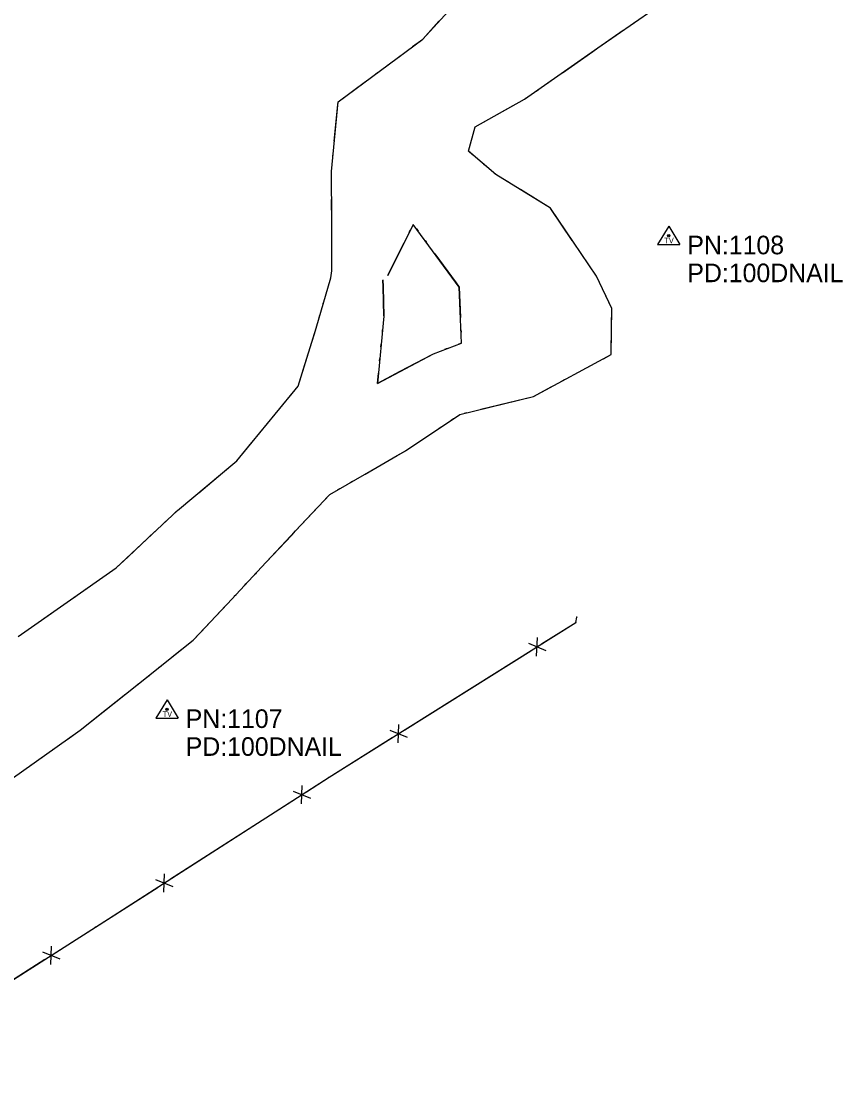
# Model space of a CAD drawing. Extents: x 1282810 to 1284464, y 402460 to 405899.
# Drawn here: x 1283550.7 to 1283771.6, y 403773 to 404059.6 of the extents above; entities that cross this region are included whole.
import ezdxf

# ---------------------------------------------------------------- set-up
doc = ezdxf.new("R2010")
doc.units = 0
for name, color, linetype in [('S_FENCE', 7, 'Continuous'), ('S_MSC_PT_SYM', 7, 'Continuous'), ('S_SECONDARY_CTL', 7, 'Continuous'), ('S_SECONDARY_CTL_ANNOT', 7, 'Continuous'), ('S_STREAM', 7, 'Continuous')]:
    doc.layers.add(name, color=color, linetype=linetype)

msp = doc.modelspace()

# ---------------------------------------------------------------- linework, layer by layer
at = {"layer": 'S_FENCE'}
for p, q in [((1283633.54, 403856.3), (1283699.83, 403897.87)), ((1283699.83, 403897.87), (1283700.13, 403899.37)), ((1283687.14, 403892.33), (1283691.75, 403890.38)), ((1283689.32, 403888.86), (1283689.57, 403893.85)), ((1283649.87, 403868.96), (1283654.48, 403867.01)), ((1283652.05, 403865.49), (1283652.3, 403870.48)), ((1283570.67, 403815.95), (1283633.54, 403856.3)), ((1283623.88, 403852.53), (1283628.51, 403850.63)), ((1283626.09, 403849.08), (1283626.29, 403854.08)), ((1283586.87, 403828.78), (1283591.49, 403826.88)), ((1283589.08, 403825.33), (1283589.28, 403830.33)), ((1283503.36, 403773.04), (1283570.67, 403815.95)), ((1283556.48, 403809.33), (1283561.09, 403807.41)), ((1283558.68, 403805.87), (1283558.88, 403810.86))]:
    msp.add_line(p, q, dxfattribs=at)
for points in [[(1283690.66, 403892.12), (1283699.83, 403897.87)], [(1283699.83, 403897.87), (1283700.13, 403899.37)], [(1283653.87, 403869.05), (1283687.75, 403890.29)], [(1283633.54, 403856.3), (1283650.48, 403866.92)], [(1283627.4, 403852.36), (1283633.54, 403856.3)], [(1283590.86, 403828.91), (1283624.51, 403850.5)], [(1283570.67, 403815.95), (1283587.5, 403826.75)], [(1283559.98, 403809.14), (1283570.67, 403815.95)], [(1283523.51, 403785.88), (1283557.1, 403807.3)]]:
    msp.add_lwpolyline(points, dxfattribs=at)
at = {"layer": 'S_MSC_PT_SYM'}
for points in [[(1283699.83, 403897.87), (1283699.83, 403897.92), (1283699.83, 403897.87), (1283699.78, 403897.87), (1283699.83, 403897.87), (1283699.83, 403897.82), (1283699.83, 403897.87), (1283699.88, 403897.87)], [(1283700.13, 403899.37), (1283700.13, 403899.42), (1283700.13, 403899.37), (1283700.08, 403899.37), (1283700.13, 403899.37), (1283700.13, 403899.32), (1283700.13, 403899.37), (1283700.18, 403899.37)], [(1283633.54, 403856.3), (1283633.54, 403856.35), (1283633.54, 403856.3), (1283633.49, 403856.3), (1283633.54, 403856.3), (1283633.54, 403856.25), (1283633.54, 403856.3), (1283633.59, 403856.3)], [(1283570.67, 403815.95), (1283570.67, 403816), (1283570.67, 403815.95), (1283570.62, 403815.95), (1283570.67, 403815.95), (1283570.67, 403815.9), (1283570.67, 403815.95), (1283570.72, 403815.95)]]:
    msp.add_lwpolyline(points, dxfattribs=at)
at = {"layer": 'S_SECONDARY_CTL'}
for p, q in [((1283724.84, 404004.55), (1283721.83, 403999.6)), ((1283724.84, 404004.55), (1283727.79, 403999.6)), ((1283721.83, 403999.6), (1283727.79, 403999.6)), ((1283589.95, 403877.14), (1283586.94, 403872.19)), ((1283589.95, 403877.14), (1283592.89, 403872.19)), ((1283586.94, 403872.19), (1283592.89, 403872.19))]:
    msp.add_line(p, q, dxfattribs=at)
for centre, radius in [((1283724.84, 404001.94), 0.311), ((1283724.84, 404001.94), 0.183), ((1283724.84, 404001.94), 0.103), ((1283589.95, 403874.53), 0.311), ((1283589.95, 403874.53), 0.183), ((1283589.95, 403874.53), 0.103)]:
    msp.add_circle(centre, radius, dxfattribs=at)
at = {"layer": 'S_STREAM'}
for points in [[(1283549.94, 403894.16), (1283563.09, 403903.37), (1283576.25, 403912.57), (1283592.73, 403928.03), (1283608.69, 403941.37), (1283616.93, 403951.42), (1283625.17, 403961.47), (1283630.02, 403977.03), (1283633.93, 403990.58), (1283634.27, 403992.53), (1283634.2, 404005.88), (1283634.12, 404019.23), (1283635.92, 404037.92), (1283647.29, 404046.35), (1283658.67, 404054.79), (1283674.36, 404072.03)], [(1283548.02, 403855.75), (1283566.59, 403868.95), (1283581.78, 403881.04), (1283596.97, 403893.13), (1283606.15, 403902.93), (1283615.32, 403912.74), (1283624.49, 403922.54), (1283633.67, 403932.34), (1283654.02, 403944.08), (1283668.68, 403953.88), (1283688.48, 403958.73), (1283709.34, 403969.96), (1283709.53, 403982.36), (1283705.39, 403991.08), (1283693, 404009.35), (1283678.32, 404018.42), (1283670.97, 404024.64), (1283672.77, 404031.24), (1283686.01, 404038.64), (1283705.76, 404052.43), (1283725.51, 404066.21)], [(1283655.97, 404052.79), (1283658.67, 404054.79), (1283663.05, 404059.61)], [(1283715.39, 404059.14), (1283715.98, 404059.56)], [(1283704.43, 404051.5), (1283705.76, 404052.43), (1283712.62, 404057.21)], [(1283652.32, 404050.08), (1283652.89, 404050.51)], [(1283696.24, 404045.78), (1283704.43, 404051.49)], [(1283649.15, 404047.73), (1283649.72, 404048.15)], [(1283645.97, 404045.37), (1283646.55, 404045.8)], [(1283692.47, 404043.15), (1283693.06, 404043.56)], [(1283635.85, 404037.23), (1283635.92, 404037.92), (1283643.3, 404043.39)], [(1283689.19, 404040.86), (1283689.78, 404041.27)], [(1283685.91, 404038.58), (1283686.01, 404038.64), (1283686.51, 404038.99)], [(1283634.91, 404027.39), (1283635.85, 404037.22)], [(1283674.25, 404032.07), (1283682.97, 404036.94)], [(1283672.09, 404023.7), (1283670.97, 404024.64), (1283672.77, 404031.24), (1283674.24, 404032.07)], [(1283634.47, 404022.87), (1283634.54, 404023.58)], [(1283675.59, 404020.73), (1283675.04, 404021.19)], [(1283634.12, 404018.93), (1283634.12, 404019.23), (1283634.16, 404019.65)], [(1283678.68, 404018.19), (1283678.32, 404018.42), (1283678.09, 404018.61)], [(1283634.15, 404014.98), (1283634.14, 404015.7)], [(1283682.08, 404016.1), (1283681.46, 404016.48)], [(1283693.29, 404008.92), (1283693, 404009.35), (1283684.95, 404014.33)], [(1283634.22, 404001.78), (1283634.2, 404005.88), (1283634.17, 404011.65)], [(1283698.9, 404000.65), (1283693.3, 404008.92)], [(1283647.92, 403990.03), (1283648.01, 403988.19), (1283648.25, 403980.3), (1283646.5, 403962.19), (1283661.61, 403970.2), (1283669.09, 403973.06), (1283668.52, 403988.14), (1283656.12, 404004.99), (1283649.33, 403991.28)], [(1283655.07, 404002.87), (1283655.38, 404003.5)], [(1283657.01, 404003.78), (1283657.42, 404003.21)], [(1283634.17, 403991.9), (1283634.27, 403992.53), (1283634.22, 404001.77)], [(1283659.3, 404000.66), (1283659.72, 404000.1)], [(1283649.33, 403991.28), (1283653.62, 403999.95)], [(1283661.94, 403997.08), (1283667.67, 403989.3)], [(1283701.48, 403996.84), (1283701.08, 403997.44)], [(1283703.72, 403993.54), (1283703.32, 403994.14)], [(1283648.25, 403980.36), (1283648.01, 403988.19), (1283647.92, 403990.02)], [(1283667.68, 403989.3), (1283668.52, 403988.14), (1283668.83, 403979.91)], [(1283705.83, 403990.15), (1283705.52, 403990.81)], [(1283633.04, 403987.5), (1283633.24, 403988.19)], [(1283709.46, 403977.63), (1283709.53, 403982.36), (1283707.28, 403987.11)], [(1283631.95, 403983.71), (1283632.15, 403984.4)], [(1283630.85, 403979.91), (1283631.05, 403980.6)], [(1283707.29, 403968.86), (1283709.34, 403969.96), (1283709.46, 403977.62)], [(1283626.98, 403967.28), (1283629.92, 403976.71)], [(1283647.83, 403975.93), (1283647.9, 403976.63)], [(1283668.96, 403976.65), (1283668.98, 403975.95)], [(1283647.46, 403972.09), (1283647.52, 403972.78)], [(1283668.84, 403972.96), (1283668.19, 403972.71)], [(1283647.09, 403968.24), (1283647.15, 403968.93)], [(1283661.1, 403969.93), (1283652.56, 403965.41)], [(1283665.23, 403971.58), (1283664.58, 403971.33)], [(1283622.77, 403958.54), (1283625.17, 403961.47), (1283626.98, 403967.28)], [(1283703.24, 403966.68), (1283703.88, 403967.02)], [(1283652.56, 403965.4), (1283646.5, 403962.19), (1283646.77, 403964.99)], [(1283696.21, 403962.89), (1283696.84, 403963.23)], [(1283699.73, 403964.79), (1283700.36, 403965.13)], [(1283684.03, 403957.64), (1283688.48, 403958.73), (1283693.24, 403961.29)], [(1283674.32, 403955.26), (1283684.02, 403957.64)], [(1283619.89, 403955.02), (1283620.34, 403955.57)], [(1283617.38, 403951.97), (1283617.84, 403952.52)], [(1283666.37, 403952.33), (1283666.97, 403952.73)], [(1283669.86, 403954.17), (1283670.56, 403954.34)], [(1283614.88, 403948.91), (1283615.33, 403949.46)], [(1283663.05, 403950.11), (1283663.65, 403950.51)], [(1283606.05, 403939.15), (1283608.69, 403941.37), (1283612.77, 403946.33)], [(1283651.85, 403942.83), (1283654.02, 403944.08), (1283660.24, 403948.24)], [(1283643.19, 403937.84), (1283651.85, 403942.82)], [(1283598.46, 403932.82), (1283606.04, 403939.15)], [(1283639.21, 403935.54), (1283639.84, 403935.9)], [(1283632.58, 403931.18), (1283633.08, 403931.71)], [(1283635.75, 403933.54), (1283636.38, 403933.91)], [(1283594.97, 403929.9), (1283595.52, 403930.36)], [(1283591.98, 403927.33), (1283592.5, 403927.81)], [(1283623.45, 403921.43), (1283624.49, 403922.54), (1283630.28, 403928.72)], [(1283589.1, 403924.62), (1283589.62, 403925.11)], [(1283579.46, 403915.59), (1283586.67, 403922.34)], [(1283616.62, 403914.13), (1283623.45, 403921.42)], [(1283571.76, 403909.43), (1283576.25, 403912.57), (1283579.46, 403915.58)], [(1283613.48, 403910.77), (1283613.98, 403911.3)], [(1283568.04, 403906.83), (1283568.63, 403907.24)], [(1283610.75, 403907.86), (1283611.25, 403908.38)], [(1283564.8, 403904.56), (1283565.39, 403904.97)], [(1283608.02, 403904.94), (1283608.52, 403905.47)], [(1283550.75, 403894.73), (1283558.84, 403900.39)], [(1283561.57, 403902.3), (1283562.15, 403902.71)], [(1283598.9, 403895.19), (1283605.72, 403902.48)], [(1283591.35, 403888.66), (1283596.97, 403893.13), (1283598.89, 403895.18)], [(1283587.76, 403885.8), (1283588.32, 403886.25)], [(1283584.63, 403883.31), (1283585.2, 403883.76)], [(1283581.51, 403880.82), (1283581.78, 403881.04), (1283582.07, 403881.27)], [(1283571.05, 403872.5), (1283578.87, 403878.72)], [(1283563.09, 403866.47), (1283566.59, 403868.95), (1283571.05, 403872.5)], [(1283559.35, 403863.8), (1283559.94, 403864.22)], [(1283556.09, 403861.49), (1283556.68, 403861.91)], [(1283552.84, 403859.17), (1283553.42, 403859.59)]]:
    msp.add_lwpolyline(points, dxfattribs=at)

# ---------------------------------------------------------------- texts
at = {"layer": 'S_SECONDARY_CTL'}
for p in [(1283723.64, 403999.93), (1283588.74, 403872.52)]:
    msp.add_text('TV', height=1.5, rotation=360, dxfattribs=at).set_placement(p)
at = {"layer": 'S_SECONDARY_CTL_ANNOT'}
for s, p in [('PN:1108', (1283729.84, 403996.94)), ('PD:100DNAIL', (1283729.84, 403989.44)), ('PN:1107', (1283594.95, 403869.53)), ('PD:100DNAIL', (1283594.95, 403862.03))]:
    msp.add_text(s, height=5, dxfattribs=at).set_placement(p)

doc.saveas('drawing.dxf')
